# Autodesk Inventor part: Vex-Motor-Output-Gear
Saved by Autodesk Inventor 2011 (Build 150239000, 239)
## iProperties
Created: 2007-08
Part Number: Vex-Motor-Output-Gear
Document SubType Name: Modeling
Density: 1 g/cm^3
Mass: 0.82152 g
Surface Area: 15.4192 cm^2
Volume: 0.82152 cm^3
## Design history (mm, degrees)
feature "Base1"
body "Solid1"
